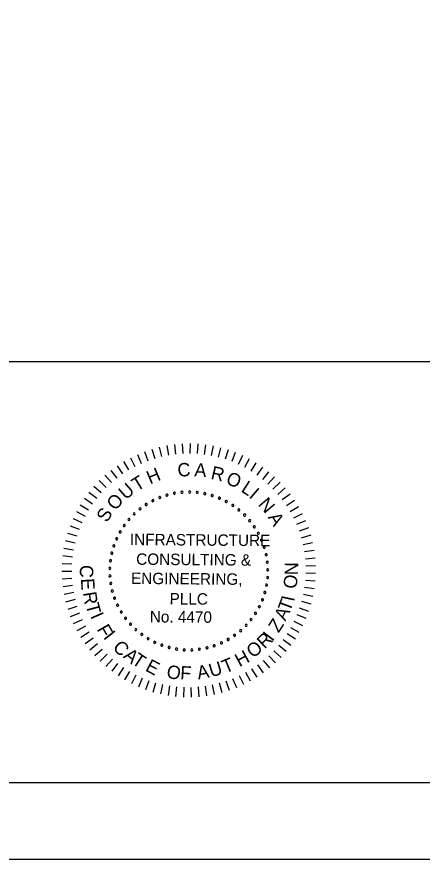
# Model space of a CAD drawing. Extents: x -121.2 to -24.9, y 6.4 to 65.5.
# Drawn here: x -53.93 to -46.88, y 6.35 to 21.02 of the extents above; entities that cross this region are included whole.
import ezdxf

# ---------------------------------------------------------------- set-up
doc = ezdxf.new("R2010")
doc.units = 0
for name, color, linetype in [('BR_BORDER LINES', 7, 'Continuous'), ('BR_TEXT', 7, 'Continuous'), ('Level 31', 7, 'Continuous')]:
    doc.layers.add(name, color=color, linetype=linetype)

msp = doc.modelspace()

# ---------------------------------------------------------------- linework, layer by layer
at = {"layer": 'BR_BORDER LINES'}
for p, q in [((-60.804, 15.017), (-46.496, 15.017)), ((-116.272, 7.683), (-26.496, 7.683))]:
    msp.add_line(p, q, dxfattribs=at)
at = {"layer": 'BR_TEXT'}
for p, q in [((-51.453, 13.526), (-51.413, 13.36)), ((-51.321, 13.553), (-51.292, 13.386)), ((-51.188, 13.572), (-51.169, 13.403)), ((-51.054, 13.583), (-51.045, 13.413)), ((-50.919, 13.586), (-50.921, 13.416)), ((-50.785, 13.58), (-50.796, 13.411)), ((-50.651, 13.567), (-50.673, 13.399)), ((-50.518, 13.545), (-50.55, 13.378)), ((-50.387, 13.515), (-50.429, 13.351)), ((-51.835, 13.396), (-51.766, 13.241)), ((-51.711, 13.447), (-51.651, 13.288)), ((-51.583, 13.49), (-51.533, 13.328)), ((-50.257, 13.478), (-50.31, 13.316)), ((-50.131, 13.432), (-50.193, 13.274)), ((-50.007, 13.379), (-50.079, 13.225)), ((-52.074, 13.272), (-51.987, 13.127)), ((-51.957, 13.338), (-51.878, 13.187)), ((-49.887, 13.318), (-49.968, 13.169)), ((-49.771, 13.251), (-49.86, 13.106)), ((-52.296, 13.12), (-52.192, 12.986)), ((-52.187, 13.2), (-52.091, 13.06)), ((-49.659, 13.176), (-49.757, 13.037)), ((-49.551, 13.094), (-49.658, 12.962)), ((-52.498, 12.942), (-52.378, 12.822)), ((-52.4, 13.034), (-52.287, 12.907)), ((-49.449, 13.006), (-49.564, 12.881)), ((-49.353, 12.913), (-49.475, 12.794)), ((-52.59, 12.844), (-52.463, 12.732)), ((-49.262, 12.813), (-49.391, 12.702)), ((-52.757, 12.633), (-52.617, 12.536)), ((-52.677, 12.741), (-52.543, 12.636)), ((-49.178, 12.708), (-49.313, 12.606)), ((-52.83, 12.52), (-52.684, 12.432)), ((-49.1, 12.598), (-49.242, 12.504)), ((-49.029, 12.484), (-49.176, 12.398)), ((-52.896, 12.402), (-52.745, 12.324)), ((-48.966, 12.365), (-49.117, 12.289)), ((-52.954, 12.281), (-52.799, 12.212)), ((-48.909, 12.243), (-49.065, 12.176)), ((-53.049, 12.029), (-52.887, 11.98)), ((-53.006, 12.157), (-52.847, 12.097)), ((-48.86, 12.117), (-49.02, 12.06)), ((-53.085, 11.9), (-52.92, 11.86)), ((-48.819, 11.989), (-48.982, 11.942)), ((-53.113, 11.768), (-52.946, 11.738)), ((-48.786, 11.859), (-48.951, 11.822)), ((-53.132, 11.635), (-52.964, 11.615)), ((-48.761, 11.727), (-48.928, 11.7)), ((-48.743, 11.593), (-48.912, 11.576)), ((-53.144, 11.501), (-52.974, 11.491)), ((-48.734, 11.459), (-48.904, 11.452)), ((-53.147, 11.366), (-52.978, 11.367)), ((-48.734, 11.324), (-48.903, 11.328)), ((-53.142, 11.231), (-52.973, 11.243)), ((-48.741, 11.19), (-48.91, 11.204)), ((-53.129, 11.097), (-52.961, 11.119)), ((-48.757, 11.056), (-48.925, 11.081)), ((-53.108, 10.965), (-52.941, 10.997)), ((-53.079, 10.833), (-52.914, 10.875)), ((-48.78, 10.923), (-48.947, 10.958)), ((-53.042, 10.704), (-52.88, 10.756)), ((-48.852, 10.664), (-49.013, 10.719)), ((-48.812, 10.793), (-48.976, 10.838)), ((-52.997, 10.577), (-52.838, 10.639)), ((-48.899, 10.538), (-49.056, 10.603)), ((-52.944, 10.453), (-52.79, 10.524)), ((-48.954, 10.415), (-49.107, 10.489)), ((-52.884, 10.333), (-52.734, 10.413)), ((-52.816, 10.216), (-52.672, 10.306)), ((-49.086, 10.181), (-49.229, 10.273)), ((-49.017, 10.296), (-49.165, 10.379)), ((-52.742, 10.104), (-52.603, 10.202)), ((-49.163, 10.07), (-49.3, 10.17)), ((-52.661, 9.996), (-52.529, 10.103)), ((-52.573, 9.894), (-52.448, 10.008)), ((-49.335, 9.863), (-49.459, 9.98)), ((-49.246, 9.964), (-49.376, 10.073)), ((-52.48, 9.797), (-52.362, 9.919)), ((-52.381, 9.706), (-52.27, 9.835)), ((-49.431, 9.768), (-49.547, 9.892)), ((-52.276, 9.622), (-52.173, 9.757)), ((-52.166, 9.543), (-52.072, 9.685)), ((-49.638, 9.597), (-49.738, 9.734)), ((-49.532, 9.679), (-49.64, 9.81)), ((-52.052, 9.472), (-51.967, 9.619)), ((-51.934, 9.408), (-51.858, 9.56)), ((-49.984, 9.389), (-50.058, 9.542)), ((-49.864, 9.451), (-49.947, 9.6)), ((-49.749, 9.521), (-49.841, 9.663)), ((-51.812, 9.351), (-51.745, 9.507)), ((-51.687, 9.302), (-51.629, 9.461)), ((-51.559, 9.26), (-51.511, 9.423)), ((-51.428, 9.226), (-51.391, 9.392)), ((-50.362, 9.249), (-50.407, 9.412)), ((-50.233, 9.288), (-50.288, 9.449)), ((-50.107, 9.335), (-50.171, 9.492)), ((-51.296, 9.2), (-51.269, 9.368)), ((-51.163, 9.183), (-51.146, 9.352)), ((-51.028, 9.173), (-51.022, 9.343)), ((-50.894, 9.172), (-50.898, 9.342)), ((-50.759, 9.179), (-50.773, 9.348)), ((-50.626, 9.194), (-50.65, 9.362)), ((-50.493, 9.217), (-50.528, 9.384))]:
    msp.add_line(p, q, dxfattribs=at)
for centre, start, end in [((-50.926, 12.743), 359.5268, 179.5268), ((-51.445, 12.647), 21.6807, 201.6807), ((-51.445, 12.647), 201.6807, 21.6807), ((-51.319, 12.689), 16.1422, 196.1422), ((-51.319, 12.689), 196.1422, 16.1422), ((-51.19, 12.72), 10.6038, 190.6038), ((-51.19, 12.72), 190.6038, 10.6038), ((-51.058, 12.738), 5.0653, 185.0653), ((-51.058, 12.738), 185.0653, 5.0653), ((-50.926, 12.743), 179.5268, 359.5268), ((-50.793, 12.735), 353.9884, 173.9884), ((-50.793, 12.735), 173.9884, 353.9884), ((-50.662, 12.714), 348.4499, 168.4499), ((-50.662, 12.714), 168.4499, 348.4499), ((-50.533, 12.681), 162.9114, 342.9114), ((-50.533, 12.681), 342.9114, 162.9114), ((-50.408, 12.636), 157.373, 337.373), ((-50.408, 12.636), 337.373, 157.373), ((-51.79, 12.449), 38.2961, 218.2961), ((-51.682, 12.526), 32.7576, 212.7576), ((-51.682, 12.526), 212.7576, 32.7576), ((-51.566, 12.592), 27.2191, 207.2191), ((-51.566, 12.592), 207.2191, 27.2191), ((-50.288, 12.579), 151.8345, 331.8345), ((-50.288, 12.579), 331.8345, 151.8345), ((-50.174, 12.51), 146.2961, 326.2961), ((-50.174, 12.51), 326.2961, 146.2961), ((-51.89, 12.362), 43.8345, 223.8345), ((-51.89, 12.362), 223.8345, 43.8345), ((-51.79, 12.449), 218.2961, 38.2961), ((-50.068, 12.431), 140.7576, 320.7576), ((-50.068, 12.431), 320.7576, 140.7576), ((-49.969, 12.342), 135.2191, 315.2191), ((-49.969, 12.342), 315.2191, 135.2191), ((-52.063, 12.16), 54.9114, 234.9114), ((-52.063, 12.16), 234.9114, 54.9114), ((-51.982, 12.265), 49.373, 229.373), ((-51.982, 12.265), 229.373, 49.373), ((-49.88, 12.244), 129.6807, 309.6807), ((-49.88, 12.244), 309.6807, 129.6807), ((-52.135, 12.048), 60.4499, 240.4499), ((-52.135, 12.048), 240.4499, 60.4499), ((-49.8, 12.137), 124.1422, 304.1422), ((-49.8, 12.137), 304.1422, 124.1422), ((-49.731, 12.024), 118.6038, 298.6038), ((-49.731, 12.024), 298.6038, 118.6038), ((-52.195, 11.93), 65.9884, 245.9884), ((-52.195, 11.93), 245.9884, 65.9884), ((-49.673, 11.904), 113.0653, 293.0653), ((-49.673, 11.904), 293.0653, 113.0653), ((-52.243, 11.806), 71.5268, 251.5268), ((-52.243, 11.806), 251.5268, 71.5268), ((-49.628, 11.779), 107.5268, 287.5268), ((-49.628, 11.779), 287.5268, 107.5268), ((-52.279, 11.678), 77.0653, 257.0653), ((-52.279, 11.678), 257.0653, 77.0653), ((-49.594, 11.651), 101.9884, 281.9884), ((-49.594, 11.651), 281.9884, 101.9884), ((-52.303, 11.547), 82.6038, 262.6038), ((-52.303, 11.547), 262.6038, 82.6038), ((-49.573, 11.519), 96.4499, 276.4499), ((-49.573, 11.519), 276.4499, 96.4499), ((-52.314, 11.415), 88.1422, 268.1422), ((-52.312, 11.282), 93.6807, 273.6807), ((-52.314, 11.415), 268.1422, 88.1422), ((-52.312, 11.282), 273.6807, 93.6807), ((-49.565, 11.387), 90.9114, 270.9114), ((-49.565, 11.387), 270.9114, 90.9114), ((-52.298, 11.15), 99.2191, 279.2191), ((-52.298, 11.15), 279.2191, 99.2191), ((-49.569, 11.254), 85.373, 265.373), ((-49.569, 11.254), 265.373, 85.373), ((-52.27, 11.02), 104.7576, 284.7576), ((-52.27, 11.02), 284.7576, 104.7576), ((-49.617, 10.993), 74.2961, 254.2961), ((-49.617, 10.993), 254.2961, 74.2961), ((-49.587, 11.122), 79.8345, 259.8345), ((-49.587, 11.122), 259.8345, 79.8345), ((-52.231, 10.893), 110.2961, 290.2961), ((-52.231, 10.893), 290.2961, 110.2961), ((-49.659, 10.867), 68.7576, 248.7576), ((-49.659, 10.867), 248.7576, 68.7576), ((-52.179, 10.771), 115.8345, 295.8345), ((-52.179, 10.771), 295.8345, 115.8345), ((-49.713, 10.746), 63.2191, 243.2191), ((-49.713, 10.746), 243.2191, 63.2191), ((-52.115, 10.654), 121.373, 301.373), ((-52.115, 10.654), 301.373, 121.373), ((-52.041, 10.544), 306.9114, 126.9114), ((-49.779, 10.63), 57.6807, 237.6807), ((-49.779, 10.63), 237.6807, 57.6807), ((-52.041, 10.544), 126.9114, 306.9114), ((-51.956, 10.441), 132.4499, 312.4499), ((-51.956, 10.441), 312.4499, 132.4499), ((-49.942, 10.421), 46.6038, 226.6038), ((-49.942, 10.421), 226.6038, 46.6038), ((-49.856, 10.522), 52.1422, 232.1422), ((-49.856, 10.522), 232.1422, 52.1422), ((-51.862, 10.348), 137.9884, 317.9884), ((-51.862, 10.348), 317.9884, 137.9884), ((-51.759, 10.263), 143.5268, 323.5268), ((-51.759, 10.263), 323.5268, 143.5268), ((-50.038, 10.329), 41.0653, 221.0653), ((-50.038, 10.329), 221.0653, 41.0653), ((-51.649, 10.189), 149.0653, 329.0653), ((-51.649, 10.189), 329.0653, 149.0653), ((-51.532, 10.126), 154.6038, 334.6038), ((-51.532, 10.126), 334.6038, 154.6038), ((-50.373, 10.115), 24.4499, 204.4499), ((-50.373, 10.115), 204.4499, 24.4499), ((-50.255, 10.175), 29.9884, 209.9884), ((-50.255, 10.175), 209.9884, 29.9884), ((-50.143, 10.247), 35.5268, 215.5268), ((-50.143, 10.247), 215.5268, 35.5268), ((-51.409, 10.075), 160.1422, 340.1422), ((-51.409, 10.075), 340.1422, 160.1422), ((-51.283, 10.036), 345.6807, 165.6807), ((-51.283, 10.036), 165.6807, 345.6807), ((-51.152, 10.009), 351.2191, 171.2191), ((-51.152, 10.009), 171.2191, 351.2191), ((-51.02, 9.995), 356.7576, 176.7576), ((-51.02, 9.995), 176.7576, 356.7576), ((-50.887, 9.993), 2.2961, 182.2961), ((-50.887, 9.993), 182.2961, 2.2961), ((-50.755, 10.005), 7.8345, 187.8345), ((-50.755, 10.005), 187.8345, 7.8345), ((-50.624, 10.029), 13.373, 193.373), ((-50.624, 10.029), 193.373, 13.373), ((-50.497, 10.066), 18.9114, 198.9114), ((-50.497, 10.066), 198.9114, 18.9114)]:
    msp.add_arc(centre, 0.0187, start, end, dxfattribs=at)
at = {"layer": 'Level 31'}
msp.add_lwpolyline([(-121.161, 6.35), (-25.161, 6.35), (-25.161, 65.017), (-121.161, 65.017)], close=True, dxfattribs=at)

# ---------------------------------------------------------------- texts
at = {"layer": 'BR_TEXT'}
for s, height, rotation, p in [('C', 0.233, 4.7281, (-51.127, 13.006)), ('A', 0.233, 355.6981, (-50.848, 13.019)), ('H', 0.233, 22.7882, (-51.615, 12.874)), ('R', 0.233, 346.6681, (-50.57, 12.974)), ('O', 0.233, 337.638, (-50.31, 12.894)), ('T', 0.233, 31.8182, (-51.841, 12.747)), ('L', 0.233, 327.108, (-50.046, 12.759)), ('U', 0.233, 40.8482, (-52.036, 12.597)), ('I', 0.233, 319.578, (-49.906, 12.659)), ('O', 0.233, 49.8782, (-52.215, 12.408)), ('N', 0.233, 310.548, (-49.744, 12.523)), ('S', 0.233, 58.9083, (-52.363, 12.199)), ('A', 0.233, 301.5179, (-49.57, 12.303)), ('INFRASTRUCTURE', 0.19939, 359.5268, (-51.966, 11.819)), ('CONSULTING &', 0.19939, 359.5268, (-51.856, 11.476)), ('C', 0.233, 267.025, (-52.829, 11.479)), ('N', 0.233, 89.2085, (-49.039, 11.293)), ('ENGINEERING,', 0.19939, 359.5268, (-51.946, 11.142)), ('E', 0.233, 273.025, (-52.818, 11.235)), ('O', 0.233, 83.2085, (-49.068, 11.05)), ('R', 0.233, 279.025, (-52.784, 10.989)), ('PLLC', 0.1994, 359.5268, (-51.275, 10.786)), ('T', 0.233, 69.3954, (-49.178, 10.645)), ('I', 0.233, 77.9093, (-49.11, 10.825)), ('T', 0.233, 285.025, (-52.737, 10.779)), ('I', 0.233, 293.7713, (-52.658, 10.584)), ('No. 4470', 0.1994, 359.5268, (-51.62, 10.474)), ('A', 0.233, 63.3954, (-49.26, 10.484)), ('F', 0.233, 299.7713, (-52.548, 10.355)), ('Z', 0.233, 57.3954, (-49.377, 10.28)), ('I', 0.233, 308.5268, (-52.436, 10.211)), ('R', 0.233, 44.5268, (-49.619, 10)), ('I', 0.233, 52.3339, (-49.487, 10.127)), ('C', 0.233, 314.5268, (-52.278, 10.024)), ('O', 0.233, 38.5268, (-49.823, 9.841)), ('A', 0.233, 320.5268, (-52.093, 9.868)), ('H', 0.233, 28.5268, (-50.058, 9.691)), ('T', 0.233, 326.5268, (-51.948, 9.765)), ('E', 0.233, 332.5268, (-51.712, 9.638)), ('T', 0.233, 22.5268, (-50.306, 9.58)), ('O', 0.233, 350.5268, (-51.338, 9.508)), ('F', 0.233, 356.5268, (-51.094, 9.483)), ('A', 0.233, 10.5268, (-50.775, 9.479)), ('U', 0.233, 16.5268, (-50.551, 9.515))]:
    msp.add_text(s, height=height, rotation=rotation, dxfattribs=at).set_placement(p)

doc.saveas('drawing.dxf')
